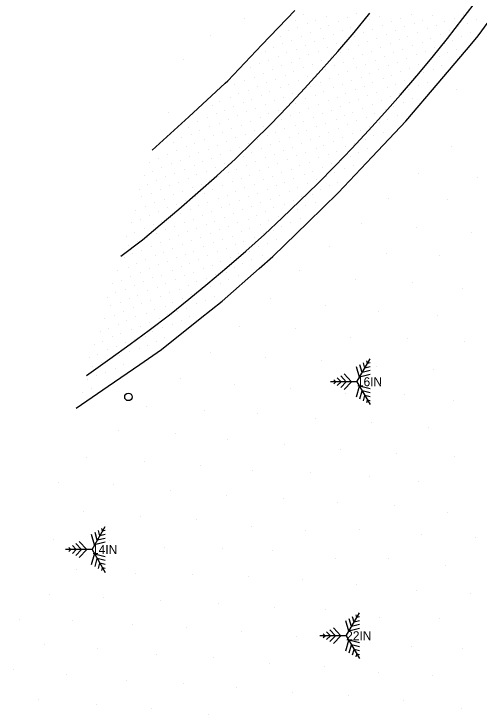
# Model space of a CAD drawing. Extents: x 1732346 to 1733076, y 467730 to 468633.
# Drawn here: x 1732478.5 to 1732572.2, y 468189.6 to 468330.7 of the extents above; entities that cross this region are included whole.
import ezdxf

# ---------------------------------------------------------------- set-up
doc = ezdxf.new("R2010")
doc.units = 0
for name, color, linetype in [('Default', 7, 'Continuous'), ('S_Ground_SpotElevation', 7, 'Continuous'), ('S_Roadway_Edge_Pavement', 7, 'Continuous'), ('S_Roadway_Painted_Lines', 7, 'Continuous'), ('S_Text', 7, 'Continuous'), ('S_Traffic_Posts', 7, 'Continuous'), ('S_Trees_Conifer_Pay', 7, 'Continuous')]:
    doc.layers.add(name, color=color, linetype=linetype)

# ---------------------------------------------------------------- blocks, each defined once
blk = doc.blocks.new('POINT_DISPLAY')
at = {"layer": 'Default'}
blk.add_line((0, 0), (0, 0), dxfattribs=at)

msp = doc.modelspace()

# ---------------------------------------------------------------- linework, layer by layer
at = {"layer": 'S_Roadway_Edge_Pavement'}
for points in [[(1732491.02, 468251.22), (1732497.44, 468255.62), (1732503.86, 468260.03), (1732508.23, 468263.02), (1732516.03, 468269.28), (1732520.4, 468272.79), (1732527.92, 468279.38), (1732530.62, 468281.75), (1732537.79, 468288.72), (1732543.83, 468294.59), (1732550.69, 468301.87), (1732557.48, 468309.07), (1732563.95, 468316.69), (1732570.43, 468324.31), (1732572.05, 468326.23), (1732577.91, 468334.33)], [(1732506.34, 468303.19), (1732513.71, 468309.95), (1732521.07, 468316.71), (1732521.57, 468317.17), (1732528.46, 468324.42), (1732535.06, 468331.36)]]:
    msp.add_lwpolyline(points, dxfattribs=at)
at = {"layer": 'S_Roadway_Painted_Lines'}
for points in [[(1732493.08, 468257.82), (1732497.79, 468261.19), (1732501.89, 468264.11), (1732505.73, 468266.94), (1732509.8, 468270.05), (1732513.72, 468273.17), (1732517.57, 468276.32), (1732521.4, 468279.54), (1732525.19, 468282.84), (1732528.95, 468286.25), (1732532.5, 468289.55), (1732536.09, 468292.99), (1732539.62, 468296.46), (1732543.2, 468300.08), (1732546.57, 468303.58), (1732549.96, 468307.19), (1732553.23, 468310.81), (1732556.36, 468314.36), (1732559.7, 468318.22), (1732562.78, 468321.89), (1732565.84, 468325.74), (1732568.94, 468329.72), (1732571.94, 468333.7)], [(1732500.04, 468281.86), (1732504.35, 468285.14), (1732507.92, 468288.16), (1732511.73, 468291.35), (1732515.56, 468294.65), (1732519.37, 468298.05), (1732523.09, 468301.5), (1732526.67, 468304.95), (1732530.15, 468308.42), (1732533.61, 468311.98), (1732537.01, 468315.63), (1732540.39, 468319.35), (1732543.72, 468323.1), (1732547.02, 468326.92), (1732550.21, 468330.8)]]:
    msp.add_lwpolyline(points, dxfattribs=at)
at = {"layer": 'S_Traffic_Posts'}
msp.add_circle((1732501.53, 468253.48), 0.749, dxfattribs=at)
at = {"layer": 'S_Trees_Conifer_Pay'}
for p, q in [((1732547.59, 468256.55), (1732550.26, 468261.16)), ((1732548.66, 468258.39), (1732548.2, 468259.97)), ((1732549.19, 468259.31), (1732548.89, 468260.36)), ((1732549.72, 468260.23), (1732549.57, 468260.76)), ((1732550.26, 468260.36), (1732549.72, 468260.23)), ((1732548.12, 468257.47), (1732547.52, 468259.57)), ((1732550.26, 468258.79), (1732548.66, 468258.39)), ((1732550.26, 468259.57), (1732549.19, 468259.31)), ((1732543.33, 468256.55), (1732542.95, 468256.94)), ((1732544.4, 468256.55), (1732543.64, 468257.33)), ((1732545.46, 468256.55), (1732544.32, 468257.73)), ((1732546.53, 468256.55), (1732545.01, 468258.13)), ((1732550.26, 468257.99), (1732548.12, 468257.47)), ((1732547.59, 468256.55), (1732542.27, 468256.55)), ((1732542.95, 468256.15), (1732543.33, 468256.55)), ((1732543.64, 468255.75), (1732544.4, 468256.55)), ((1732544.32, 468255.36), (1732545.46, 468256.55)), ((1732545.01, 468254.96), (1732546.53, 468256.55)), ((1732547.52, 468253.52), (1732548.12, 468255.62)), ((1732547.59, 468256.55), (1732550.26, 468251.93)), ((1732550.26, 468255.1), (1732548.12, 468255.62)), ((1732548.2, 468253.12), (1732548.66, 468254.7)), ((1732550.26, 468254.3), (1732548.66, 468254.7)), ((1732548.89, 468252.72), (1732549.19, 468253.78)), ((1732550.26, 468253.52), (1732549.19, 468253.78)), ((1732549.57, 468252.33), (1732549.72, 468252.86)), ((1732550.26, 468252.72), (1732549.72, 468252.86)), ((1732494.2, 468222.73), (1732496.86, 468227.34)), ((1732494.73, 468223.66), (1732494.12, 468225.76)), ((1732495.26, 468224.58), (1732494.81, 468226.16)), ((1732495.79, 468225.5), (1732495.49, 468226.55)), ((1732496.86, 468225.76), (1732495.79, 468225.5)), ((1732496.33, 468226.42), (1732496.18, 468226.95)), ((1732496.86, 468226.55), (1732496.33, 468226.42)), ((1732496.86, 468224.97), (1732495.26, 468224.58)), ((1732489.94, 468222.73), (1732489.56, 468223.13)), ((1732491, 468222.73), (1732490.24, 468223.52)), ((1732492.07, 468222.73), (1732490.93, 468223.92)), ((1732493.13, 468222.73), (1732491.61, 468224.32)), ((1732496.86, 468224.18), (1732494.73, 468223.66)), ((1732494.2, 468222.73), (1732488.87, 468222.73)), ((1732489.56, 468222.34), (1732489.94, 468222.73)), ((1732490.24, 468221.94), (1732491, 468222.73)), ((1732490.93, 468221.55), (1732492.07, 468222.73)), ((1732491.61, 468221.15), (1732493.13, 468222.73)), ((1732494.12, 468219.71), (1732494.73, 468221.81)), ((1732494.2, 468222.73), (1732496.86, 468218.12)), ((1732496.86, 468221.28), (1732494.73, 468221.81)), ((1732494.81, 468219.31), (1732495.26, 468220.89)), ((1732496.86, 468220.49), (1732495.26, 468220.89)), ((1732495.49, 468218.91), (1732495.79, 468219.97)), ((1732496.86, 468219.71), (1732495.79, 468219.97)), ((1732496.18, 468218.52), (1732496.33, 468219.05)), ((1732496.86, 468218.91), (1732496.33, 468219.05)), ((1732545.43, 468205.35), (1732548.1, 468209.96)), ((1732547.03, 468208.11), (1732546.73, 468209.17)), ((1732547.56, 468209.04), (1732547.41, 468209.57)), ((1732548.1, 468209.17), (1732547.56, 468209.04)), ((1732545.97, 468206.27), (1732545.36, 468208.38)), ((1732546.5, 468207.19), (1732546.04, 468208.77)), ((1732548.1, 468207.59), (1732546.5, 468207.19)), ((1732548.1, 468208.38), (1732547.03, 468208.11)), ((1732542.24, 468205.35), (1732541.48, 468206.14)), ((1732543.31, 468205.35), (1732542.16, 468206.54)), ((1732544.37, 468205.35), (1732542.85, 468206.93)), ((1732548.1, 468206.8), (1732545.97, 468206.27)), ((1732545.43, 468205.35), (1732540.11, 468205.35)), ((1732541.17, 468205.35), (1732540.8, 468205.74)), ((1732540.8, 468204.96), (1732541.17, 468205.35)), ((1732541.48, 468204.56), (1732542.24, 468205.35)), ((1732542.16, 468204.16), (1732543.31, 468205.35)), ((1732542.85, 468203.77), (1732544.37, 468205.35)), ((1732545.43, 468205.35), (1732548.1, 468200.74)), ((1732545.36, 468202.32), (1732545.97, 468204.43)), ((1732548.1, 468203.9), (1732545.97, 468204.43)), ((1732546.04, 468201.92), (1732546.5, 468203.5)), ((1732548.1, 468203.11), (1732546.5, 468203.5)), ((1732546.73, 468201.53), (1732547.03, 468202.58)), ((1732548.1, 468202.32), (1732547.03, 468202.58)), ((1732547.41, 468201.13), (1732547.56, 468201.66)), ((1732548.1, 468201.53), (1732547.56, 468201.66))]:
    msp.add_line(p, q, dxfattribs=at)

# ---------------------------------------------------------------- block references
at = {"layer": 'S_Ground_SpotElevation'}
for p in [(1732536.84, 468330.58), (1732541.38, 468330.25), (1732547.6, 468330.66), (1732552.05, 468330.25), (1732558.64, 468330.57), (1732562.83, 468330.27), (1732569.17, 468330.46), (1732525, 468329.84), (1732535.22, 468329.36), (1732537.61, 468328.79), (1732539.22, 468329.4), (1732543.88, 468329.14), (1732545.62, 468329.86), (1732550.13, 468329.49), (1732554.61, 468329.18), (1732556.39, 468329.84), (1732559.14, 468328.76), (1732560.73, 468329.32), (1732565.22, 468329.08), (1732567.29, 468329.8), (1732569.86, 468328.82), (1732571.73, 468329.55), (1732535.65, 468328.03), (1732540.34, 468327.66), (1732541.93, 468328.37), (1732546.4, 468328), (1732548.3, 468328.4), (1732550.83, 468327.63), (1732552.76, 468328.42), (1732557.25, 468328.05), (1732561.84, 468327.66), (1732563.66, 468328.41), (1732567.99, 468328.06), (1732518.12, 468326.32), (1732532.22, 468326.16), (1732533.85, 468327.26), (1732536.36, 468326.12), (1732538.21, 468326.83), (1732542.83, 468326.57), (1732544.73, 468327.28), (1732547.17, 468326.19), (1732548.97, 468326.91), (1732553.49, 468326.54), (1732555.35, 468327.32), (1732557.79, 468326.1), (1732559.78, 468326.93), (1732564.48, 468326.58), (1732566.16, 468327.32), (1732568.77, 468326.17), (1732570.42, 468326.85), (1732532.66, 468324.63), (1732534.5, 468325.38), (1732539.1, 468325.08), (1732540.93, 468325.81), (1732543.48, 468324.66), (1732545.44, 468325.01), (1732549.74, 468325.07), (1732551.53, 468325.77), (1732554.36, 468324.66), (1732556.1, 468325.45), (1732560.73, 468325), (1732562.39, 468325.79), (1732565.33, 468324.66), (1732566.78, 468325.41), (1732530.86, 468323.88), (1732535.47, 468323.55), (1732537.22, 468324.32), (1732539.91, 468323.2), (1732541.66, 468323.96), (1732545.94, 468323.44), (1732547.95, 468324.34), (1732550.47, 468323.2), (1732552.27, 468323.81), (1732556.87, 468323.54), (1732558.78, 468324.35), (1732561.39, 468323.14), (1732563.18, 468323.96), (1732567.65, 468323.56), (1732529.24, 468323.01), (1732531.75, 468322.08), (1732533.5, 468322.82), (1732536.05, 468321.7), (1732537.9, 468322.46), (1732542.51, 468322.09), (1732544.22, 468322.8), (1732546.98, 468321.71), (1732548.81, 468322.49), (1732553.06, 468322.06), (1732555.05, 468322.85), (1732557.6, 468321.71), (1732559.58, 468322.41), (1732564.15, 468322.1), (1732565.76, 468322.86), (1732512.74, 468321.5), (1732527.87, 468320.59), (1732529.86, 468321.3), (1732534.36, 468320.97), (1732538.59, 468320.56), (1732540.49, 468321.35), (1732544.95, 468320.98), (1732549.3, 468320.54), (1732551.3, 468321.3), (1732555.79, 468320.98), (1732560.08, 468320.55), (1732561.92, 468320.89), (1732526.24, 468319.81), (1732530.49, 468319.47), (1732532.36, 468320.19), (1732534.89, 468319.08), (1732536.88, 468319.86), (1732541.31, 468319.47), (1732543.13, 468320.22), (1732545.61, 468319.04), (1732547.55, 468319.85), (1732552.01, 468319.49), (1732554, 468320.27), (1732556.41, 468319.09), (1732558.13, 468319.73), (1732562.95, 468319.52), (1732564.71, 468320.27), (1732526.9, 468317.94), (1732528.67, 468318.74), (1732531.21, 468317.54), (1732533.2, 468318.36), (1732537.68, 468317.97), (1732539.5, 468318.76), (1732542.14, 468317.56), (1732543.85, 468318.38), (1732548.47, 468317.93), (1732550.08, 468318.73), (1732552.87, 468317.65), (1732554.49, 468318.32), (1732559.1, 468318.03), (1732560.96, 468318.79), (1732522.98, 468316.38), (1732524.93, 468317.24), (1732527.57, 468316.06), (1732529.44, 468316.86), (1732533.73, 468316.42), (1732535.76, 468317.27), (1732538.25, 468316.07), (1732540.23, 468316.85), (1732544.66, 468316.53), (1732546.56, 468317.27), (1732549.05, 468316.1), (1732550.76, 468316.82), (1732555.31, 468316.52), (1732557.27, 468317.24), (1732560.01, 468316.15), (1732561.74, 468316.93), (1732525.69, 468315.34), (1732530.02, 468314.98), (1732532.12, 468315.78), (1732536.53, 468315.41), (1732540.89, 468315.03), (1732542.86, 468315.79), (1732547.22, 468315.37), (1732551.58, 468314.91), (1732553.68, 468315.78), (1732556.27, 468314.69), (1732557.99, 468315.45), (1732567.62, 468315.42), (1732522.19, 468313.86), (1732523.79, 468314.61), (1732526.44, 468313.5), (1732528.34, 468314.29), (1732532.86, 468313.88), (1732534.59, 468314.61), (1732537.18, 468313.55), (1732539.15, 468314.28), (1732543.69, 468313.88), (1732545.34, 468314.61), (1732547.88, 468313.52), (1732549.66, 468314.2), (1732554.43, 468313.95), (1732558.88, 468313.58), (1732518.56, 468312.3), (1732519.95, 468313.03), (1732522.68, 468312.03), (1732524.65, 468312.74), (1732529.14, 468312.43), (1732530.94, 468313.14), (1732533.49, 468312.03), (1732535.26, 468312.65), (1732539.89, 468312.43), (1732541.81, 468313.13), (1732544.29, 468312.05), (1732546.06, 468312.81), (1732550.68, 468312.38), (1732552.49, 468313.16), (1732555.02, 468312.09), (1732557.01, 468312.85), (1732509.59, 468310.9), (1732519.21, 468310.52), (1732520.86, 468311.27), (1732525.39, 468310.95), (1732527.21, 468311.66), (1732529.84, 468310.57), (1732531.78, 468311.27), (1732536.12, 468310.9), (1732537.86, 468311.64), (1732540.64, 468310.57), (1732542.42, 468311.3), (1732546.7, 468310.88), (1732548.74, 468311.68), (1732551.22, 468310.55), (1732553.29, 468311.34), (1732515.37, 468309.06), (1732517.46, 468309.71), (1732521.7, 468309.43), (1732523.61, 468310.17), (1732526.18, 468309.02), (1732528.11, 468309.79), (1732532.37, 468309.44), (1732534.23, 468310.18), (1732536.88, 468309.07), (1732538.88, 468309.8), (1732543.38, 468309.42), (1732545.13, 468310.22), (1732547.56, 468309.11), (1732549.54, 468309.74), (1732553.8, 468309.35), (1732555.76, 468310.22), (1732513.74, 468307.85), (1732517.8, 468307.9), (1732519.89, 468308.62), (1732522.31, 468307.59), (1732524.24, 468308.27), (1732528.79, 468307.98), (1732530.55, 468308.7), (1732533.06, 468307.58), (1732535.24, 468308.27), (1732539.54, 468307.98), (1732541.17, 468308.67), (1732545.77, 468308.29), (1732550.05, 468307.91), (1732552.15, 468308.73), (1732514.22, 468306.43), (1732515.94, 468307.11), (1732520.58, 468306.79), (1732525.1, 468306.42), (1732526.96, 468307.22), (1732531.14, 468306.81), (1732535.73, 468306.5), (1732537.46, 468307.19), (1732541.92, 468306.79), (1732543.84, 468307.55), (1732546.63, 468306.48), (1732548.24, 468307.12), (1732552.88, 468306.83), (1732510.71, 468304.82), (1732512.32, 468305.72), (1732516.84, 468305.33), (1732518.69, 468306.09), (1732521.29, 468304.96), (1732523.17, 468305.72), (1732527.52, 468305.34), (1732529.54, 468306.12), (1732532.09, 468304.98), (1732533.96, 468305.68), (1732538.19, 468305.33), (1732540.11, 468306.04), (1732542.85, 468305), (1732544.67, 468305.74), (1732549.28, 468305.29), (1732550.99, 468306.12), (1732513.17, 468303.86), (1732514.86, 468304.54), (1732517.65, 468303.42), (1732519.49, 468304.2), (1732523.92, 468303.84), (1732525.76, 468304.55), (1732528.41, 468303.52), (1732530.19, 468304.26), (1732534.59, 468303.8), (1732536.5, 468304.62), (1732539.36, 468303.45), (1732540.9, 468304.24), (1732545.39, 468303.91), (1732547.13, 468304.56), (1732549.8, 468303.53), (1732566.56, 468304.01), (1732509.48, 468302.37), (1732511.21, 468303.07), (1732513.92, 468301.97), (1732515.75, 468302.7), (1732520.19, 468302.34), (1732522.02, 468303.13), (1732524.67, 468302), (1732526.3, 468302.7), (1732530.89, 468302.39), (1732532.79, 468303.16), (1732535.43, 468302.04), (1732537.26, 468302.79), (1732541.85, 468302.37), (1732543.48, 468303.02), (1732546.3, 468301.97), (1732547.93, 468302.73), (1732505.72, 468300.8), (1732507.64, 468301.57), (1732511.96, 468301.21), (1732516.43, 468300.85), (1732518.34, 468301.6), (1732520.89, 468300.53), (1732522.78, 468301.29), (1732527.21, 468300.85), (1732529.08, 468301.66), (1732531.58, 468300.53), (1732533.51, 468301.3), (1732538.07, 468300.82), (1732539.88, 468301.67), (1732542.54, 468300.57), (1732544.48, 468301.05), (1732508.11, 468299.71), (1732510.21, 468300.44), (1732512.83, 468299.31), (1732514.79, 468300.05), (1732519.17, 468299.78), (1732523.42, 468299.4), (1732525.32, 468300.13), (1732529.79, 468299.79), (1732534.35, 468299.31), (1732536.07, 468300.15), (1732540.56, 468299.81), (1732545.19, 468299.43), (1732546.95, 468300.13), (1732504.74, 468298.19), (1732506.3, 468298.96), (1732509.06, 468297.9), (1732510.82, 468298.61), (1732515.33, 468298.29), (1732517.37, 468298.97), (1732519.76, 468297.9), (1732521.73, 468298.65), (1732525.98, 468298.18), (1732527.88, 468299.03), (1732530.62, 468297.88), (1732532.45, 468298.64), (1732536.97, 468298.32), (1732538.6, 468298.95), (1732541.49, 468297.94), (1732543.16, 468298.65), (1732560.05, 468298.56), (1732571.8, 468297.79), (1732505.32, 468296.33), (1732507.2, 468297.17), (1732511.56, 468296.77), (1732513.59, 468297.53), (1732516.25, 468296.39), (1732517.95, 468297.19), (1732522.46, 468296.81), (1732524.31, 468297.55), (1732526.88, 468296.31), (1732528.75, 468297.21), (1732533.05, 468296.78), (1732534.9, 468297.41), (1732537.63, 468296.4), (1732539.49, 468297.22), (1732543.78, 468296.76), (1732503.8, 468295.26), (1732508, 468295.24), (1732509.9, 468296.01), (1732512.45, 468294.94), (1732514.36, 468295.69), (1732518.55, 468295.27), (1732520.58, 468296.08), (1732523.13, 468294.96), (1732524.94, 468295.68), (1732529.48, 468295.34), (1732531.44, 468296.08), (1732533.91, 468294.91), (1732535.62, 468295.66), (1732540.21, 468295.34), (1732542.12, 468296.01), (1732504.18, 468293.81), (1732506.26, 468294.51), (1732510.64, 468294.2), (1732515.02, 468293.85), (1732516.82, 468294.56), (1732521.43, 468294.16), (1732525.68, 468293.84), (1732527.52, 468294.53), (1732531.93, 468294.13), (1732536.51, 468293.8), (1732538.73, 468294.37), (1732506.84, 468292.7), (1732508.85, 468293.36), (1732511.28, 468292.33), (1732513.11, 468293.09), (1732517.52, 468292.7), (1732519.63, 468293.42), (1732521.91, 468292.29), (1732523.87, 468293.02), (1732528.2, 468292.66), (1732530.2, 468293.34), (1732532.91, 468292.24), (1732534.75, 468293.12), (1732539.25, 468292.75), (1732553.99, 468293.39), (1732565.84, 468293.18), (1732502.96, 468291.15), (1732504.9, 468291.82), (1732507.67, 468290.8), (1732509.47, 468291.6), (1732514.01, 468291.22), (1732515.69, 468291.99), (1732518.36, 468290.88), (1732520.22, 468291.62), (1732524.57, 468291.25), (1732526.36, 468291.96), (1732529.14, 468290.87), (1732530.86, 468291.62), (1732535.53, 468291.24), (1732537.31, 468292.01), (1732503.98, 468289.34), (1732505.74, 468290.05), (1732510.1, 468289.62), (1732512.04, 468290.48), (1732514.56, 468289.34), (1732516.38, 468290.06), (1732520.82, 468289.73), (1732522.65, 468290.43), (1732525.67, 468289.29), (1732527.38, 468290.1), (1732531.84, 468289.75), (1732533.49, 468290.48), (1732536.21, 468289.38), (1732502.08, 468288.61), (1732506.58, 468288.2), (1732508.17, 468288.91), (1732510.74, 468287.82), (1732512.83, 468288.59), (1732517.18, 468288.27), (1732518.96, 468288.93), (1732521.67, 468287.89), (1732523.44, 468288.56), (1732528.06, 468288.23), (1732529.72, 468288.96), (1732532.47, 468287.9), (1732534.16, 468288.6), (1732548.49, 468288.49), (1732502.75, 468286.71), (1732504.69, 468287.49), (1732509.01, 468287.13), (1732513.5, 468286.75), (1732515.36, 468287.46), (1732519.8, 468287.15), (1732524.4, 468286.79), (1732525.94, 468287.46), (1732528.73, 468286.43), (1732530.82, 468287.1), (1732559.63, 468287.66), (1732570.73, 468286.53), (1732501.16, 468285.89), (1732505.3, 468285.65), (1732507.18, 468286.39), (1732509.88, 468285.26), (1732511.63, 468285.99), (1732516.15, 468285.63), (1732518.03, 468286.36), (1732520.54, 468285.28), (1732522.55, 468285.91), (1732526.99, 468285.58), (1732531.42, 468285.29), (1732501.49, 468284.09), (1732503.43, 468284.89), (1732506.15, 468283.8), (1732507.91, 468284.54), (1732512.43, 468284.17), (1732514.32, 468284.93), (1732516.73, 468283.74), (1732518.73, 468284.55), (1732523.15, 468284.2), (1732524.82, 468284.83), (1732527.67, 468283.83), (1732529.62, 468284.46), (1732542.06, 468283.75), (1732502.29, 468282.29), (1732504.12, 468283.03), (1732508.54, 468282.62), (1732510.51, 468283.42), (1732513.06, 468282.28), (1732514.75, 468282.86), (1732519.46, 468282.7), (1732521.27, 468283.45), (1732523.79, 468282.29), (1732526.04, 468282.8), (1732553.53, 468282.48), (1732500.65, 468281.52), (1732504.96, 468281.21), (1732506.9, 468281.89), (1732509.39, 468280.83), (1732511.29, 468281.56), (1732515.76, 468281.22), (1732517.54, 468281.92), (1732522.02, 468281.57), (1732526.44, 468281.22), (1732528.53, 468281.92), (1732564.32, 468281.99), (1732501.46, 468279.66), (1732503.2, 468280.44), (1732507.64, 468280.09), (1732512.19, 468279.69), (1732513.85, 468280.47), (1732518.39, 468280.06), (1732520.1, 468280.72), (1732522.94, 468279.6), (1732524.59, 468280.46), (1732499.42, 468278.97), (1732503.9, 468278.61), (1732505.7, 468279.32), (1732508.28, 468278.03), (1732510.4, 468278.91), (1732514.68, 468278.52), (1732516.72, 468279.29), (1732519.11, 468278.24), (1732521.29, 468278.62), (1732536.04, 468279.03), (1732500.11, 468276.98), (1732502.03, 468277.82), (1732504.61, 468276.75), (1732506.41, 468277.45), (1732510.98, 468277.13), (1732512.85, 468277.87), (1732515.36, 468276.76), (1732517.3, 468277.44), (1732521.75, 468277.14), (1732523.7, 468277.87), (1732547.4, 468277.07), (1732498.29, 468276.36), (1732500.92, 468275.22), (1732502.81, 468276.01), (1732507.45, 468275.54), (1732509.01, 468276.35), (1732511.84, 468275.22), (1732513.67, 468275.95), (1732518.03, 468275.66), (1732520.03, 468276.32), (1732558.87, 468276.49), (1732568.93, 468275.39), (1732498.97, 468274.48), (1732503.32, 468273.99), (1732505.35, 468274.89), (1732507.96, 468273.75), (1732509.77, 468274.48), (1732514.22, 468274.11), (1732516.2, 468274.86), (1732518.79, 468273.8), (1732497.41, 468273.62), (1732499.91, 468272.59), (1732501.74, 468273.36), (1732505.98, 468272.9), (1732510.42, 468272.56), (1732512.51, 468273.39), (1732517.08, 468273), (1732530.09, 468273.28), (1732497.94, 468271.86), (1732502.58, 468271.46), (1732504.13, 468272.26), (1732506.86, 468271.17), (1732508.98, 468271.78), (1732513.24, 468271.39), (1732515.23, 468272.21), (1732541.24, 468271.83), (1732498.75, 468269.97), (1732500.48, 468270.72), (1732503.03, 468269.62), (1732505.11, 468270.35), (1732509.49, 468270.02), (1732511.49, 468270.73), (1732513.94, 468269.68), (1732552, 468270.74), (1732563.74, 468269.89), (1732496.78, 468269.2), (1732499.56, 468268.15), (1732501.07, 468268.85), (1732505.87, 468268.51), (1732507.76, 468269.29), (1732512.2, 468268.9), (1732495.84, 468266.69), (1732497.58, 468267.36), (1732502.16, 468267.07), (1732504.01, 468267.76), (1732506.41, 468266.7), (1732508.46, 468267.4), (1732510.46, 468268.01), (1732523.9, 468267.65), (1732535.28, 468267.18), (1732498.25, 468265.59), (1732500.01, 468266.29), (1732504.91, 468265.67), (1732508.9, 468265.5), (1732546.26, 468265.53), (1732494.61, 468264.09), (1732496.39, 468264.72), (1732500.98, 468264.46), (1732502.77, 468265.05), (1732507.26, 468264.7), (1732557.89, 468265.21), (1732569.18, 468264.57), (1732497.31, 468262.98), (1732499.08, 468263.68), (1732501.75, 468262.61), (1732503.72, 468263.3), (1732505.46, 468263.8), (1732518.09, 468262.51), (1732493.76, 468261.36), (1732495.29, 468262.12), (1732497.8, 468261.05), (1732499.81, 468261.85), (1732529.21, 468261.38), (1732494.29, 468259.63), (1732496.09, 468260.4), (1732500.59, 468259.95), (1732540.36, 468260.73), (1732496.89, 468258.48), (1732498.91, 468259.13), (1732551.63, 468259.59), (1732562.95, 468258.95), (1732493.33, 468256.98), (1732495.01, 468257.79), (1732511.94, 468257.26), (1732522.89, 468256.03), (1732492.2, 468254.36), (1732494.06, 468255.13), (1732534.16, 468255.18), (1732545.35, 468254.23), (1732557.12, 468254.06), (1732567.14, 468252.74), (1732505.24, 468251.61), (1732516.83, 468250.82), (1732527.6, 468250.05), (1732539.24, 468249.06), (1732550.62, 468248.23), (1732562.02, 468247.41), (1732499.57, 468246.71), (1732511.06, 468246.12), (1732521.49, 468244.87), (1732532.92, 468243.99), (1732544.37, 468242.93), (1732493.04, 468241.3), (1732555.53, 468242.06), (1732567.32, 468241.53), (1732504.76, 468240.49), (1732516.01, 468239.71), (1732526.63, 468238.61), (1732538.33, 468238.22), (1732550.08, 468237.49), (1732487.44, 468236.19), (1732498.56, 468235.76), (1732560.05, 468236.48), (1732509.99, 468234.59), (1732521.23, 468233.54), (1732532.77, 468233), (1732543.72, 468232.23), (1732555.11, 468231.59), (1732492.4, 468230.34), (1732565.95, 468230.19), (1732503.96, 468229.3), (1732515.28, 468228.74), (1732526.28, 468227.39), (1732537.29, 468226.53), (1732548.03, 468226.78), (1732486.37, 468224.81), (1732497.78, 468224.54), (1732560.56, 468225.73), (1732571.55, 468225.07), (1732508.86, 468223.15), (1732520.46, 468223.03), (1732530.56, 468222.48), (1732543.18, 468220.85), (1732554.01, 468220.83), (1732491.07, 468218.79), (1732565.5, 468219.54), (1732502.91, 468217.87), (1732514.45, 468217.75), (1732525.8, 468217.19), (1732536.59, 468216.66), (1732547.6, 468215.65), (1732485.67, 468213.67), (1732496.47, 468213.05), (1732559.66, 468214.41), (1732570.51, 468213.96), (1732507.91, 468212.43), (1732519.73, 468211.84), (1732530.9, 468211.12), (1732541.36, 468210.54), (1732552.23, 468209.11), (1732479.64, 468208.61), (1732490.36, 468208.39), (1732502.32, 468207.65), (1732564.3, 468208.74), (1732513.19, 468207.05), (1732524.41, 468206.25), (1732535.45, 468205.16), (1732484.53, 468203.65), (1732547.22, 468204.39), (1732558.57, 468203.22), (1732495.33, 468202.82), (1732568.97, 468202.68), (1732507.29, 468201.65), (1732518.6, 468200.96), (1732529.92, 468199.69), (1732541.11, 468199.1), (1732478.47, 468198.48), (1732551.85, 468197.99), (1732488.99, 468197.5), (1732501.05, 468196.35), (1732562.8, 468197.33), (1732512.62, 468195.67), (1732523.3, 468194.89), (1732534.67, 468193.99), (1732483.38, 468192.47), (1732545.89, 468193.21), (1732557.07, 468192.3), (1732495.04, 468191.39), (1732506.12, 468190.69), (1732568.75, 468190.6), (1732517.66, 468189.57)]:
    msp.add_blockref('POINT_DISPLAY', p, dxfattribs=at)

# ---------------------------------------------------------------- texts
at = {"layer": 'S_Text'}
for s, p in [('16IN', (1732547.59, 468255.64)), ('14IN', (1732494.2, 468221.83)), ('22IN', (1732545.43, 468204.45))]:
    msp.add_text(s, height=1.8, dxfattribs=at).set_placement(p)

doc.saveas('drawing.dxf')
